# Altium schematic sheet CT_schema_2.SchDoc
size 461 x 297 mm
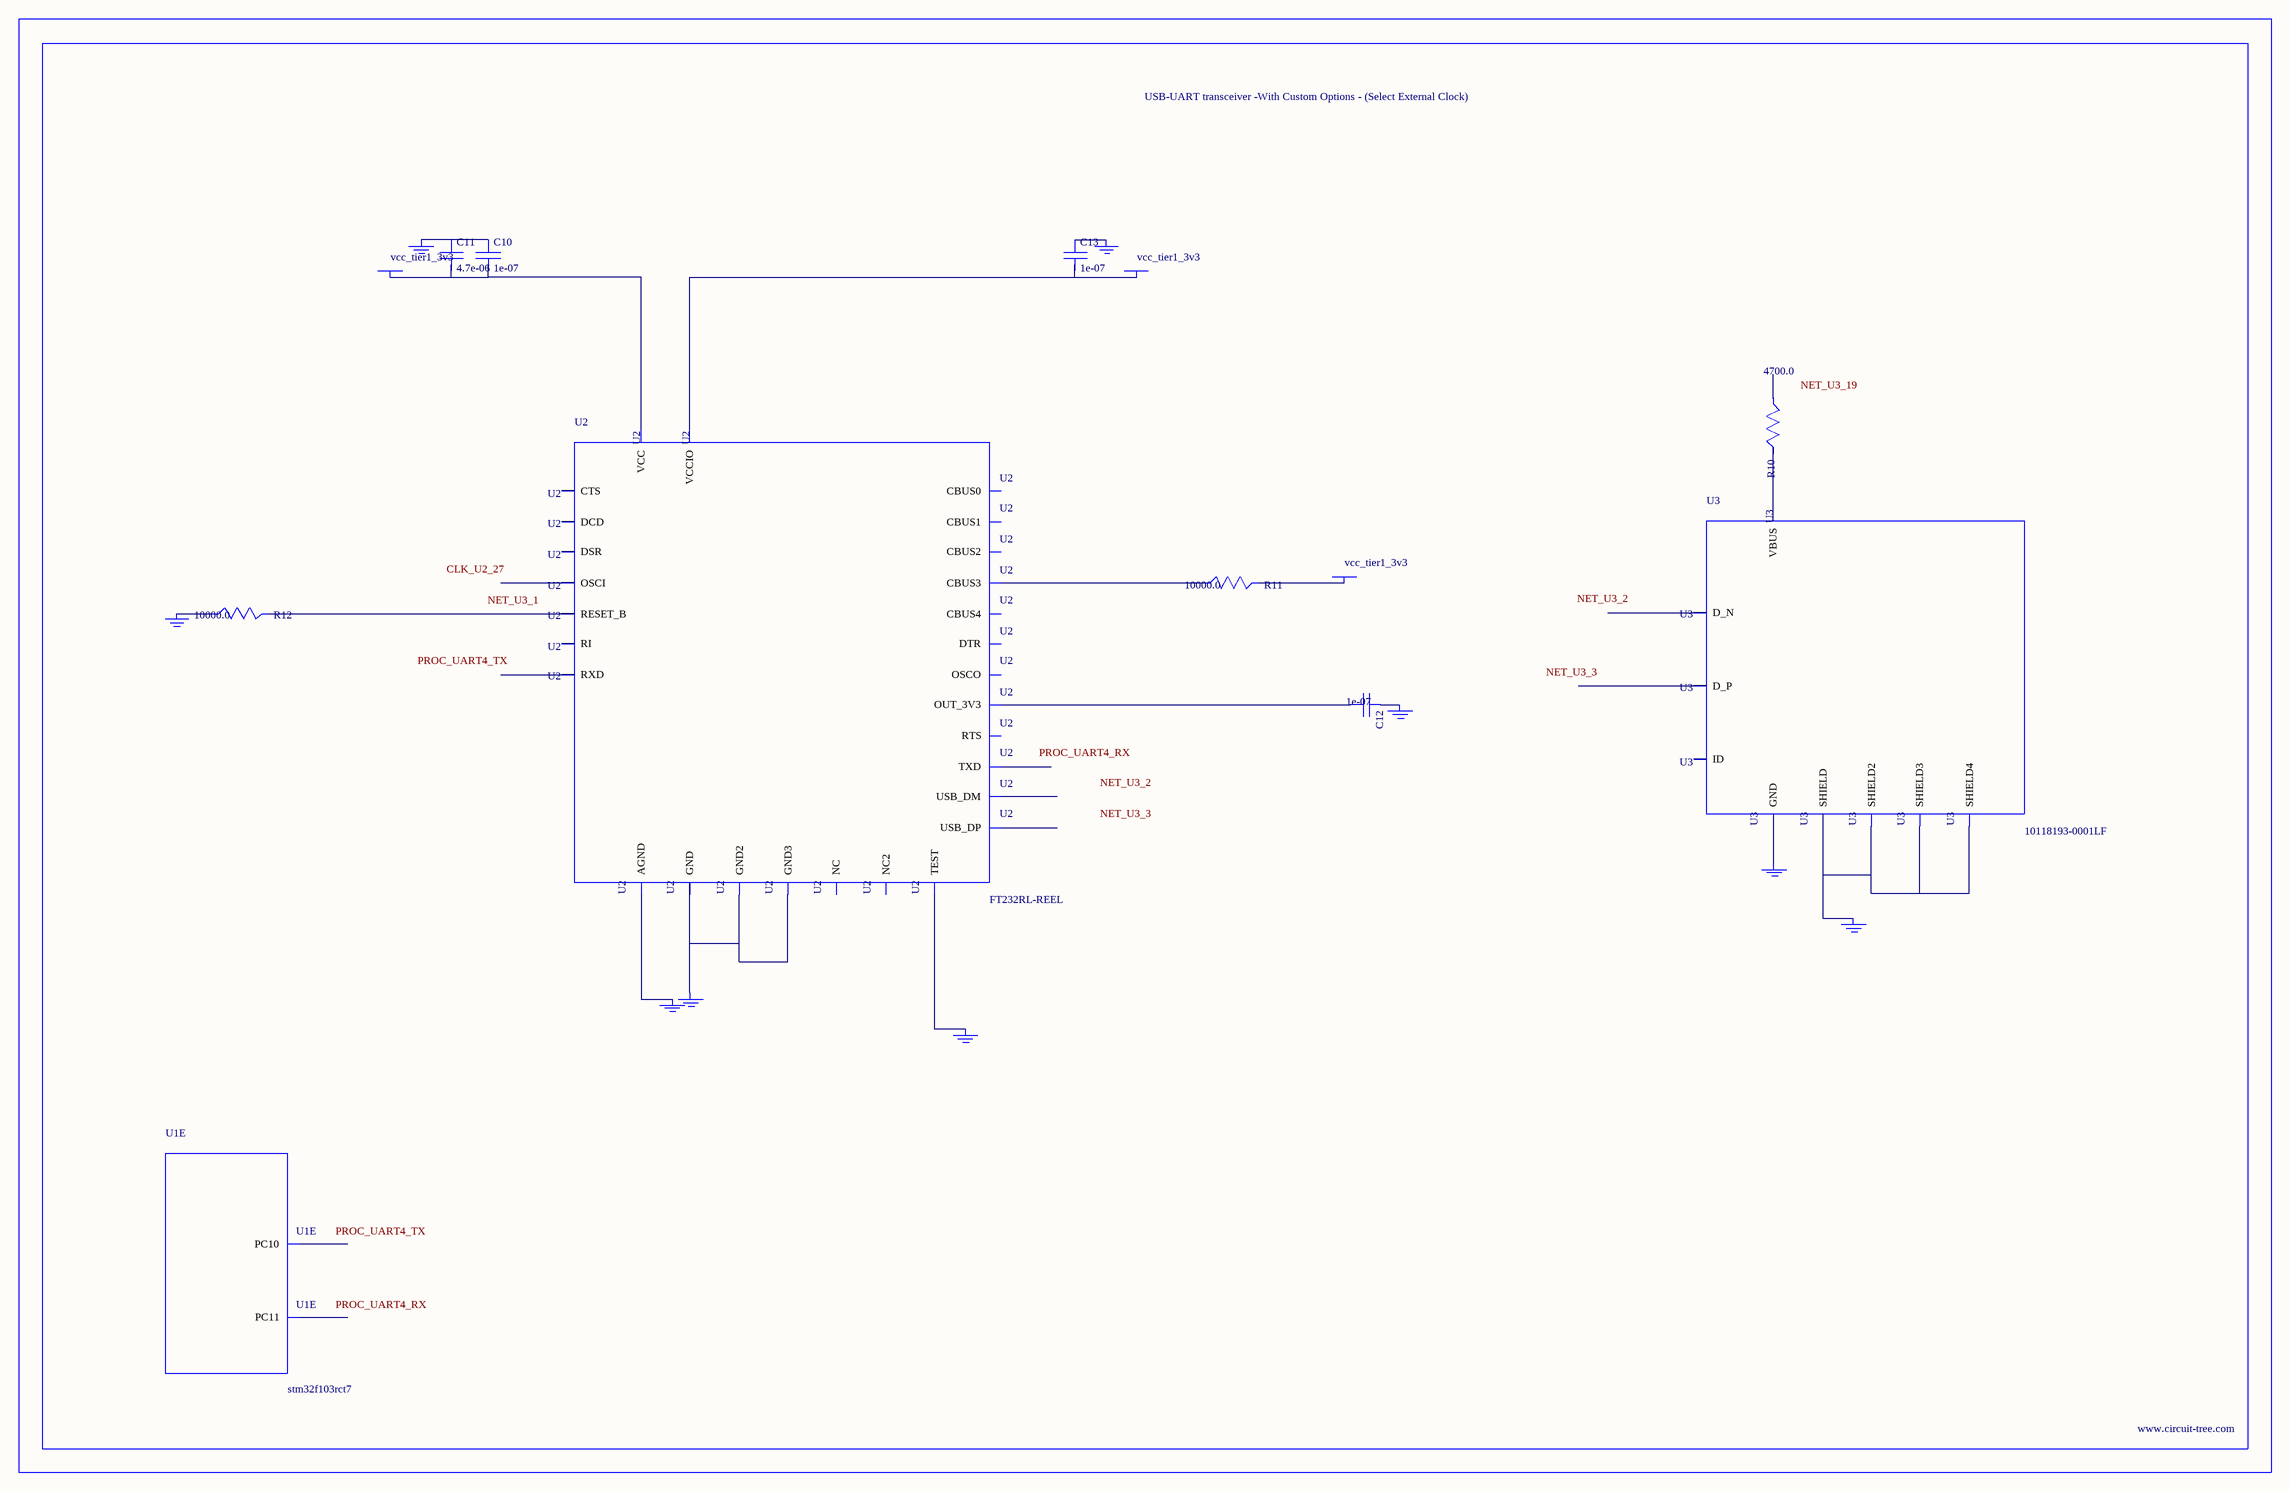
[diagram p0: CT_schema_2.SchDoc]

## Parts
BORDER1  (no value)
C10  1e-07  [C0402]
C11  4.7e-06  [C0805]
C12  1e-07  [C0402]
C13  1e-07  [C0402]
GND_INSTANCE_1_0  (no value)
GND_INSTANCE_1_1  (no value)
GND_INSTANCE_1_2  (no value)
GND_INSTANCE_1_3  (no value)
GND_INSTANCE_1_4  (no value)
GND_INSTANCE_1_5  (no value)
GND_INSTANCE_1_6  (no value)
GND_INSTANCE_1_7  (no value)
GND_INSTANCE_1_8  (no value)
POWER_INSTANCE_1_0  vcc_tier1_3v3
POWER_INSTANCE_1_1  vcc_tier1_3v3
POWER_INSTANCE_1_2  vcc_tier1_3v3
R10  4700.0  [R0603]
R11  10000.0  [R0603]
R12  10000.0  [R0603]
U1  stm32f103rct7  [LQFP64]  (part E of 9)
U2  FT232RL-REEL  [SSOP-28]
U3  10118193-0001LF  [FCI_10118193-0001LF]

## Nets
NetC10_1: C10.1 C11.1 GND_INSTANCE_1_3.0(GND)
NetC10_2: C10.2 C11.2 POWER_INSTANCE_1_2.0(PWR) U2.20(VCC)
NetC12_1: C12.1 GND_INSTANCE_1_1.0(GND)
NetC12_2: C12.2 U2.17(OUT_3V3)
NetC13_1: C13.1 GND_INSTANCE_1_0.0(GND)
NetC13_2: C13.2 POWER_INSTANCE_1_0.0(PWR) U2.4(VCCIO)
NetGND_INSTANCE_1_2_0: GND_INSTANCE_1_2.0(GND) R12.1
NetGND_INSTANCE_1_4_0: GND_INSTANCE_1_4.0(GND) U2.25(AGND)
NetGND_INSTANCE_1_5_0: GND_INSTANCE_1_5.0(GND) U2.26(TEST)
NetGND_INSTANCE_1_6_0: GND_INSTANCE_1_6.0(GND) U2.7(GND) U2.18(GND2) U2.21(GND3)
NetGND_INSTANCE_1_7_0: GND_INSTANCE_1_7.0(GND) U3.6(SHIELD) U3.7(SHIELD2) U3.8(SHIELD3) U3.9(SHIELD4)
NetGND_INSTANCE_1_8_0: GND_INSTANCE_1_8.0(GND) U3.5(GND)
NetPOWER_INSTANCE_1_1_0: POWER_INSTANCE_1_1.0(PWR) R11.2
NetR10_2: R10.2 U3.1(VBUS)
NetR11_1: R11.1 U2.14(CBUS3)
NetR12_2: R12.2 U2.19(RESET_B)

Not connected (* = marked no-connect by the designer): R10 1; U1 51(PC10) 52(PC11); U2 1(TXD) 2(DTR) 3(RTS) 5(RXD) 6(RI) 8(NC) 9(DSR) 10(DCD) 11(CTS) 12(CBUS4) 13(CBUS2) 15(USB_DP) 16(USB_DM) 22(CBUS1) 23(CBUS0) 24(NC2) 27(OSCI) 28(OSCO); U3 2(D_N) 3(D_P) 4(ID)

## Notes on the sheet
- Labels drawn without touching a wire or pin: CLK_U2_27, NET_U3_1, NET_U3_2, NET_U3_3, NET_U3_19, PROC_UART4_RX, PROC_UART4_TX

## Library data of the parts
BORDER1 = BORDER_PAGE1
C10 C12 C13 = C0402C104K3RACTU
C11 = C0805C475K4RACTU
GND_INSTANCE_1_0-GND_INSTANCE_1_8 = GND
POWER_INSTANCE_1_0-POWER_INSTANCE_1_2 = PWR
R10 = RC0603JR-074K7L
R11 R12 = RC0603JR-0710KL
